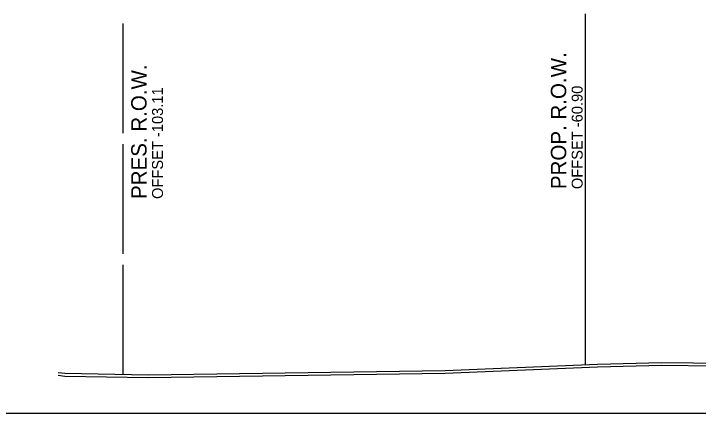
# Model space of a CAD drawing. Extents: x -192 to 2669, y -25 to 8040.
# Drawn here: x 36.9 to 99.4, y 5500 to 5536.4 of the extents above; entities that cross this region are included whole.
import ezdxf

# ---------------------------------------------------------------- set-up
doc = ezdxf.new("R2010")
doc.units = 0
for name, color, linetype in [('DESIGN - ROW - Right-of-Way and Easement Labels', 7, 'Continuous'), ('DESIGN - ROW - Right-of-Way Linework', 7, 'Continuous'), ('DESIGN - SHEET - Light Grid', 7, 'Continuous'), ('SURVEY - GROUND - Bottom of Topsoil Layer', 7, 'Continuous'), ('SURVEY - GROUND - Top of Ground', 7, 'Continuous'), ('SURVEY - PROPERTY - ROW Lines', 7, 'Continuous'), ('SURVEY - PROPERTY - ROW Lines Text', 7, 'Continuous')]:
    doc.layers.add(name, color=color, linetype=linetype)

msp = doc.modelspace()

# ---------------------------------------------------------------- linework, layer by layer
at = {"layer": 'DESIGN - ROW - Right-of-Way Linework'}
msp.add_line((89.1, 5504.447), (89.1, 5536.447), dxfattribs=at)
at = {"layer": 'DESIGN - SHEET - Light Grid'}
msp.add_line((0, 5500), (150, 5500), dxfattribs=at)
at = {"layer": 'SURVEY - GROUND - Bottom of Topsoil Layer'}
for p, q in [((76.288, 5503.657), (90.196, 5504.243)), ((90.196, 5504.243), (96.066, 5504.381)), ((96.066, 5504.381), (116.242, 5504.159)), ((40.982, 5503.479), (41.585, 5503.398)), ((41.585, 5503.398), (49.176, 5503.254)), ((49.176, 5503.254), (76.288, 5503.657))]:
    msp.add_line(p, q, dxfattribs=at)
at = {"layer": 'SURVEY - GROUND - Top of Ground'}
msp.add_lwpolyline([(40.982, 5503.729), (41.585, 5503.648), (49.176, 5503.504), (76.288, 5503.907), (90.196, 5504.493), (96.066, 5504.631), (116.242, 5504.409)], dxfattribs=at)
at = {"layer": 'SURVEY - PROPERTY - ROW Lines'}
for p, q in [((46.889, 5525.548), (46.889, 5535.548)), ((46.889, 5514.548), (46.889, 5524.548)), ((46.889, 5503.548), (46.889, 5513.548))]:
    msp.add_line(p, q, dxfattribs=at)

# ---------------------------------------------------------------- texts
at = {"layer": 'DESIGN - ROW - Right-of-Way and Easement Labels'}
for s, height, p in [('PROP. R.O.W.', 1.4, (87.35, 5520.447)), ('OFFSET -60.90', 1, (88.85, 5520.447))]:
    msp.add_text(s, height=height, rotation=90, dxfattribs=at).set_placement(p)
at = {"layer": 'SURVEY - PROPERTY - ROW Lines Text'}
for s, height, p in [('PRES. R.O.W.', 1.4, (49.039, 5519.548)), ('OFFSET -103.11', 1, (50.539, 5519.548))]:
    msp.add_text(s, height=height, rotation=90, dxfattribs=at).set_placement(p)

doc.saveas('drawing.dxf')
